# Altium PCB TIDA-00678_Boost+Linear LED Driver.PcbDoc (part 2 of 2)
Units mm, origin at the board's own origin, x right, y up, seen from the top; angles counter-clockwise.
Board outline 111.76 x 61.72 mm, 2 copper layers (Top Layer, Bottom Layer), stack 1.575 mm thick; 183 components, 81 nets, 485 pads, 326 vias.
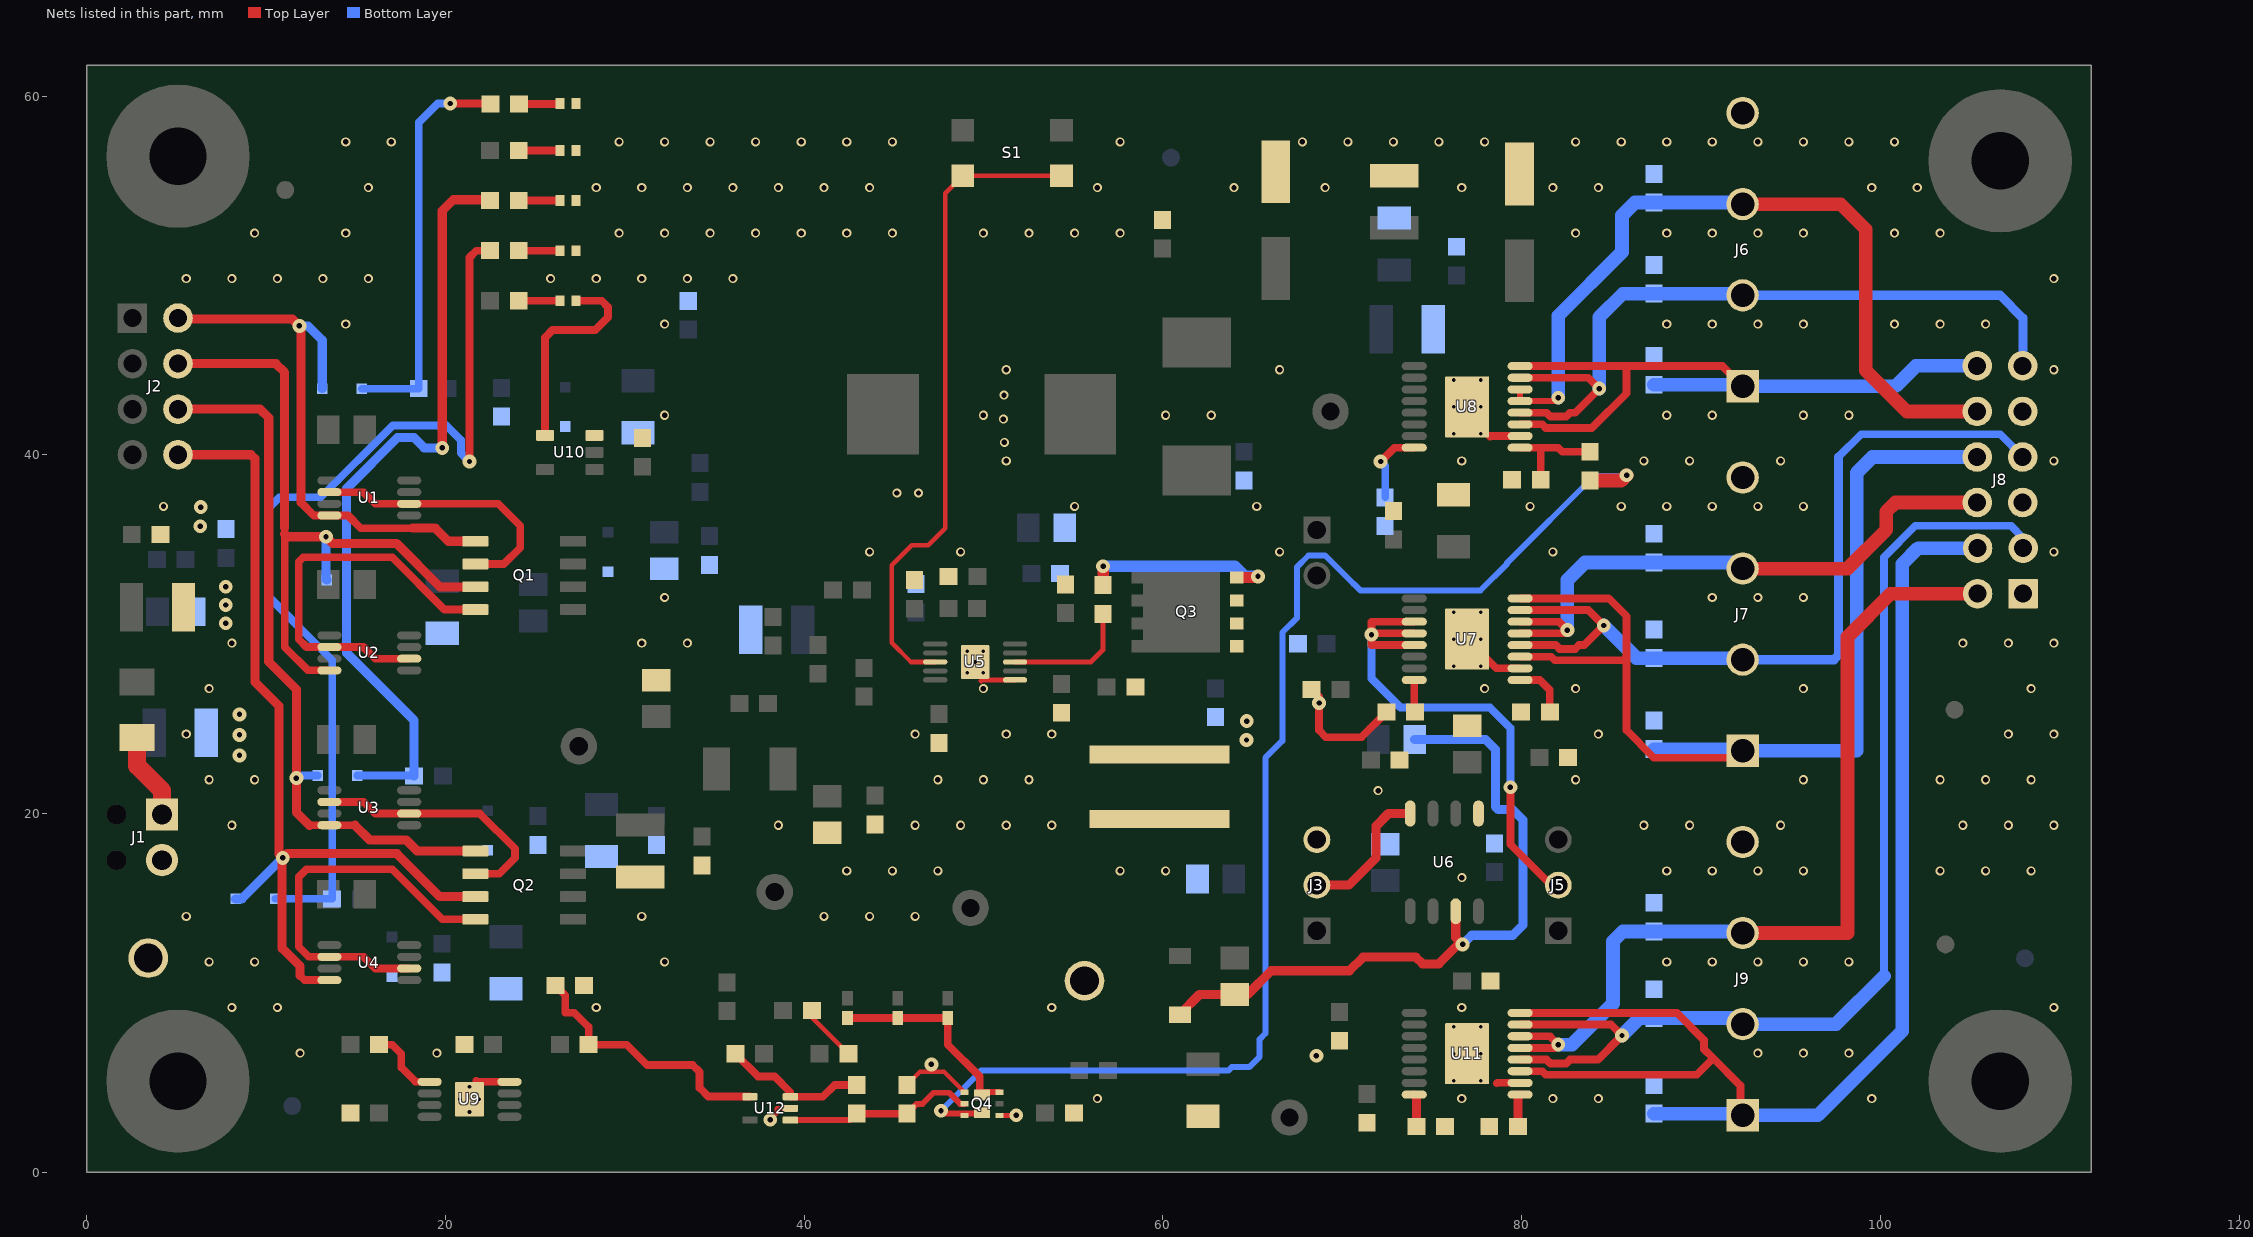
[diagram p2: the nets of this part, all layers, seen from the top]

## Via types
v1: diameter 0.508, hole 0.305, Top Layer to Bottom Layer, tented both sides, 203 vias
v2: diameter 0.77, hole 0.3, Top Layer to Bottom Layer, tented both sides, 96 vias
v3: diameter 0.4, hole 0.2, Top Layer to Bottom Layer, 18 vias
v4: diameter 0.5, hole 0.2, Top Layer to Bottom Layer, 9 vias

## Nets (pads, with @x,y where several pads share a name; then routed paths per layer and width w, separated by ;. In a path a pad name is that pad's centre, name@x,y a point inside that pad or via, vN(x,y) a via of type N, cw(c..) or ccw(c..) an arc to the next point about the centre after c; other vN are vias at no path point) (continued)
NetC67_2: C67.2 Q4.5 R42.1 U12.1 | length 10.6
  Top Layer w0.33: U12.1@39.225,2.906 42.568,2.906 R42.1@42.926,3.264 ; C67.2@45.72,3.264 46.266,3.81 46.592,3.81 47.211,4.429 48.076,4.429 48.695,3.81 Q4.5@48.936,3.81
  Top Layer w0.432: R42.1@42.926,3.264 C67.2@45.72,3.264
NetD2_2: D2.2 R13.1 R14.2 U6.7 | length 39.2
  Top Layer w0.508: D2.2@60.96,8.777 60.96,8.826 62.04,9.906 R14.2@64.008,9.906 64.716,9.906 66.04,11.23 70.397,11.23 71.159,11.992 74.098,11.992 74.479,11.611 75.381,11.611 76.47,12.7 v2(76.708,12.7) 76.327,13.081 U6.7@76.327,14.547
  Bottom Layer w0.508: R13.1@74.041,24.13 77.978,24.13 78.536,23.572 78.536,20.375 78.696,20.215 79.499,20.215 80.083,19.631 80.083,13.789 79.502,13.208 77.216,13.208 v2(76.708,12.7)
NetD3_1: D3.1 R11.2 R15.1 | length 43.7
  Top Layer w0.508: v2(19.812,40.386) 19.812,53.599 20.437,54.224 22.432,54.224 R11.2@22.479,54.177
  Bottom Layer w0.432: D3.1@15.07,22.12 18.228,22.12 R15.1@18.25,22.098
  Bottom Layer w0.508: R15.1@18.25,22.098 18.25,25.184 14.478,28.956 14.478,38.116 17.329,40.967 18.231,40.967 18.812,40.386 v2(19.812,40.386)
NetD4_1: D4.1 R12.2 R16.1 | length 22.5
  Top Layer w0.432: v2(20.259,59.587) 22.475,59.587 R12.2@22.506,59.556
  Bottom Layer w0.432: D4.1@15.324,43.688 R16.1@18.504,43.688 18.504,58.526 19.566,59.587 v2(20.259,59.587)
NetD6_2: D6.2 R11.1 | length 2.3
  Top Layer w0.432: R11.1@24.079,54.177 D6.2@26.385,54.177
NetD8_2: D8.2 R12.1 | length 2.3
  Top Layer w0.432: R12.1@24.106,59.556 26.353,59.556 D8.2@26.384,59.586
NetD10_2: D10.2 R17.1 | length 2.3
  Top Layer w0.432: R17.1@24.079,56.971 D10.2@26.385,56.971
NetD12_1: D12.1 R31.2 R32.1 | length 53.6
  Top Layer w0.432: v2(21.336,39.624) 21.336,50.999 21.72,51.383 R31.2@22.479,51.383 R31.2@22.432,51.43
  Bottom Layer w0.432: D12.1@10.498,15.24 R32.1@13.678,15.24 13.678,28.543 10.125,32.096 10.125,37.011 10.741,37.627 13.041,37.627 17.051,41.637 20.047,41.637 20.863,40.821 20.863,40.097 v2(21.336,39.624)
NetD13_2: D13.2 R31.1 | length 2.3
  Top Layer w0.432: R31.1@24.079,51.383 D13.2@26.385,51.383
NetD15_1: D15.1 U10.4 | length 11.9
  Top Layer w0.432: U10.4@25.549,41.082 25.549,46.541 25.963,46.956 28.344,46.956 29.058,47.67 29.058,48.235 28.704,48.589 D15.1@27.285,48.589
NetD15_2: D15.2 R34.1 | length 2.3
  Top Layer w0.432: R34.1@24.079,48.589 D15.2@26.385,48.589
NetD16_1: D16.1 D17.1 D18.1 Q4.3 Q4.8 | length 11.5
  Top Layer w0.33: Q4.8@49.784,4.554 49.878,4.46 Q4.3@50.886,4.46
  Top Layer w0.432: D16.1@42.418,8.594 D17.1@45.212,8.594 D18.1@48.006,8.594 48.006,7.112 49.784,5.334 Q4.8@49.784,4.554
NetJ1_1: J1.1 L1.1 | length 4.9
  Top Layer w1.016: L1.1@2.794,24.231 2.794,22.666 4.191,21.269 J1.1@4.191,19.939
NetJ3_2: J3.2 U6.4 | length 7.9
  Top Layer w0.508: J3.2@68.58,16.002 70.358,16.002 71.882,17.526 71.882,19.304 72.575,19.997 U6.4@73.787,19.997
NetJ5_2: J5.2 U7.3 U7.4 U7.5 | length 29.9
  Top Layer w0.432: U7.5@74.012,29.393 71.628,29.393 v2(71.628,29.972) v2@71.628,30.043 ; U7.4@74.012,30.043 v2@71.628,30.043 ; U7.3@74.012,30.693 71.646,30.693 71.628,30.675 v2@71.628,30.043 ; v2(79.375,21.463) 79.375,18.288 81.661,16.002 J5.2@82.042,16.002
  Bottom Layer w0.432: v2(71.628,29.972) 71.628,27.526 73.246,25.908 78.232,25.908 79.375,24.765 v2(79.375,21.463)
NetQ1_2: Q1.2 U1.2 U1.6 | length 15.5
  Top Layer w0.432: U1.2@13.523,37.917 15.423,37.917 16.073,37.267 U1.6@17.973,37.267 22.931,37.267 24.159,36.039 24.159,34.827 23.241,33.909 Q1.2@21.659,33.909
NetQ1_4: Q1.4 U2.2 U2.6 | length 22.1
  Top Layer w0.432: U2.6@17.973,28.631 16.073,28.631 15.423,29.281 U2.2@13.523,29.281 12.248,29.281 11.811,29.718 11.811,34.036 12.065,34.29 17.018,34.29 19.939,31.369 Q1.4@21.659,31.369
NetQ2_2: Q2.2 U3.2 U3.6 | length 14.5
  Top Layer w0.432: U3.2@13.523,20.645 15.423,20.645 16.073,19.995 U3.6@17.973,19.995 21.915,19.995 23.876,18.034 23.876,17.526 22.987,16.637 Q2.2@21.659,16.637
NetQ2_4: Q2.4 U4.2 U4.6 | length 21.7
  Top Layer w0.432: U4.6@17.973,11.359 16.073,11.359 15.423,12.009 U4.2@13.523,12.009 12.375,12.009 11.811,12.573 11.811,16.459 12.246,16.894 17.018,16.894 19.815,14.097 Q2.4@21.659,14.097
NetQ3_1: Q3.1 Q3.2 Q3.3 R7.2 R8.2 R9.1
  other v2: 64.659,24.099 64.677,25.151
NetQ3_4: Q3.4 R6.2 | length 11.1
  Top Layer w0.635: R6.2@56.662,32.752 v2(56.662,33.786) ; Q3.4@64.117,33.159 65.241,33.159 v2(65.301,33.219)
  Bottom Layer w0.635: v2(56.662,33.786) 64.019,33.786 64.586,33.219 v2(65.301,33.219)
NetQ4_6: Q4.6 Q4.7 R29.1 | length 74
  Top Layer w0.33: v2(47.625,3.429) 47.774,3.28 49.911,3.28 Q4.7@49.911,3.322
  Top Layer w0.762: R29.1@83.82,38.57 85.56,38.57 v2(85.852,38.862)
  Bottom Layer w0.33: v2@47.498,3.556 v2(47.625,3.429) 49.86,5.664 63.643,5.664 63.837,5.858 64.803,5.858 65.389,6.444 65.389,7.41 65.713,7.734 65.713,23.101 66.661,24.049 66.661,30.09 67.465,30.894 67.465,33.736 68.118,34.389 69.042,34.389 70.628,32.803 70.642,32.803 71.006,32.439 77.711,32.439 79.194,33.922 79.194,33.982 84.032,38.82 85.81,38.82 v2(85.852,38.862)
NetR6_1: R6.1 U5.8 | length 7.2
  Top Layer w0.279: U5.8@51.755,28.448 55.983,28.448 56.646,29.111 R6.1@56.646,31.135
NetR25_2: R25.2 U7.8 | length 1.8
  Top Layer w0.432: U7.8@74.012,27.443 74.012,25.706 R25.2@74.064,25.654
NetR26_2: R26.2 U8.8 | length 4.3
  Top Layer w0.432: v2(72.136,39.624) 72.909,40.397 U8.8@74.012,40.397
  Bottom Layer w0.432: v2(72.136,39.624) 72.39,39.37 R26.2@72.39,37.63
NetR27_2: R27.2 U7.9 | length 3.1
  Top Layer w0.432: U7.9@79.912,27.443 81.015,27.443 81.572,26.886 R27.2@81.572,25.654
NetR28_2: R28.2 R29.2 U8.9 | length 5.8
  Top Layer w0.432: U8.9@79.912,40.397 81.026,40.397 ; R28.2@81.064,38.608 81.064,40.359 81.026,40.397 ; R29.2@83.82,40.17 82.258,40.17 82.031,40.397 81.026,40.397
NetR30_1: R30.1 U9.5 | length 4.1
  Top Layer w0.432: R30.1@16.294,7.112 17.018,7.112 17.526,6.604 17.526,5.842 18.329,5.039 U9.5@19.111,5.039
NetR37_1: R37.1 R38.2 U12.4 | length 15.1
  Top Layer w0.432: R38.2@26.124,10.414 26.67,9.868 26.67,8.89 27.178,8.89 27.978,8.09 R37.1@27.978,7.112 30.099,7.112 31.242,5.969 33.782,5.969 34.163,5.588 34.163,4.699 34.64,4.222 36.959,4.222 U12.4@36.975,4.206
NetR39_2: R39.2 R42.2 U12.3 | length 8.2
  Top Layer w0.432: R39.2@36.157,6.604 37.427,5.334 38.354,5.334 39.225,4.463 U12.3@39.225,4.206 41.036,4.206 41.694,4.864 R42.2@42.926,4.864
NetR40_2: R40.2 U11.8 | length 1.8
  Top Layer w0.508: U11.8@74.012,4.3 74.13,4.182 R40.2@74.13,2.54
NetR41_2: R41.2 U11.9 | length 1.8
  Top Layer w0.508: R41.2@79.794,2.54 79.794,4.182 U11.9@79.912,4.3
NetS1_3: S1.3 S1.4 U5.3 | length 36.6
  Top Layer w0.254: U5.3@47.305,28.448 45.948,28.448 44.873,29.523 44.873,33.832 45.993,34.952 46.905,34.952 47.855,35.902 47.855,54.578 S1.3@48.838,55.56 S1.4@54.338,55.56
REV1: C68.2 J8.4 J9.1 U11.11 U11.16 | length 73.8
  Top Layer w0.432: U11.11@79.912,5.629 81.145,5.629 81.345,5.429 89.757,5.429 90.678,6.35 ; U11.16@79.912,8.879 88.657,8.879 90.17,7.366 90.17,6.858 90.678,6.35 ; J9.1@92.202,2.794 92.202,4.826 90.678,6.35
  Bottom Layer w0.762: C68.2@87.378,3.264 92.11,3.264 ccw(c92.11,3.394) J9.1@92.202,3.302 ; J9.1@92.324,3.175 96.52,3.175 101.219,7.874 101.219,33.909 102.108,34.798 J8.4@105.41,34.798
REV2: C66.2 J8.3 J9.2 U11.12 U11.15 | length 61.3
  Top Layer w0.432: U11.12@79.912,6.279 81.389,6.279 81.607,6.061 82.477,6.061 82.695,6.279 84.257,6.279 v2(85.598,7.62) 84.989,8.229 U11.15@79.912,8.229
  Bottom Layer w0.432: 100.203,10.922 100.203,34.29 101.952,36.039 107.286,36.039 107.95,35.375 J8.3@107.95,34.798
  Bottom Layer w0.762: v2(85.598,7.62) 86.576,8.598 C66.2@87.378,8.598 91.981,8.598 J9.2@92.324,8.255 97.536,8.255 100.203,10.922
REV3: C64.2 J8.2 J9.3 U11.13 U11.14 | length 50.6
  Top Layer w0.432: U11.13@79.912,6.929 81.859,6.929 v2(82.042,7.112) 81.575,7.579 U11.14@79.912,7.579
  Top Layer w0.762: J9.3@92.324,13.335 98.171,13.335 98.171,29.845 100.584,32.258 J8.2@105.41,32.258
  Bottom Layer w0.762: v2(82.042,7.112) 82.804,7.112 85.09,9.398 85.09,12.878 85.636,13.424 C64.2@87.378,13.424 J9.3@91.732,13.424 ; J9.3@92.202,12.954 J9.3@91.732,13.424 ; J9.3@92.202,13.462 cw(c92.11,13.554) 92.11,13.424 J9.3@91.732,13.424
REVGND: C1.2 C2.2 C3.2 C4.2 C5.2 C10.2 C11.2 C12.2 C13.2 C14.2 C15.2 C16.2 C17.2 C20.1 C21.1 C22.1 C23.2 C24.2 C26.2 C27.2 C28.2 C29.2 C30.2 C31.2 C32.1 C33.1 C34.2 C35.1 C36.1 C37.1 C38.2 C39.1 C40.2 C41.1 C42.2 C43.2 C44.1 C45.1 C46.2 C47.2 C48.2 C49.1 C50.1 C51.1 C52.1 C53.1 C54.1 C55.2 C56.1 C57.2 C58.1 C59.2 C60.1 C61.2 C62.1 C63.2 C64.1 C65.1 C66.1 C67.1 C68.1 D6.1 D7.2 D8.1 D9.2 D10.1 D11.2 D13.1 D14.2 GND_1.1 GND_2.1 J1.2 J3.3 J6.4 J7.4 J8.1 J8.5 J8.9 J9.4 Q4.1 Q4.4 R5.1 R8.1 R18.1 R19.1 R23.1 R24.1 R25.1 R26.1 R27.1 R28.1 R33.1 R36.1 R38.1 R40.1 R41.1 U5.6 U5.11 U6.1 U7.10 U7.17 U8.10 U8.17 U9.4 U9.9 U10.3 U11.10 U11.17 U12.2 | length 27.6
  Top Layer w0.254: v2@38.1,3.175 v2(38.1,2.921) 38.481,3.302 38.481,3.556 U12.2@39.225,3.556 ; C67.1@45.72,4.864 46.444,5.588 47.808,5.588 Q4.4@48.936,4.46 ; Q4.1@50.886,3.16 51.801,3.16 v2(51.816,3.175)
  Top Layer w0.279: C63.2@40.424,9.017 40.424,8.636 R36.1@42.456,6.604 ; 49.862,27.376 49.934,27.448 U5.6@51.755,27.448
  Top Layer w0.432: 21.717,5.08 21.758,5.039 U9.4@23.661,5.039 ; C42.2@68.288,26.924 68.707,26.505 v2(68.707,26.162) 68.707,24.638 69.088,24.257 71.067,24.257 R25.1@72.464,25.654 ; U7.17@76.962,29.718 78.587,28.093 U7.10@79.912,28.093 ; 78.232,41.021 78.258,41.047 U8.10@80.012,41.047 ; 78.613,4.953 78.639,4.979 U11.10@80.012,4.979
  other v1: 56.341,4.103 76.661,4.103 81.741,4.103 84.281,4.103 99.521,4.103 11.891,6.643 19.511,6.643 93.171,6.643 95.711,6.643 98.251,6.643 8.081,9.183 10.621,9.183 28.401,9.183 53.801,9.183 76.661,9.183 109.681,9.183 6.811,11.723 9.351,11.723 32.211,11.723 88.091,11.723 90.631,11.723 93.171,11.723 95.711,11.723 98.251,11.723 5.541,14.263 30.941,14.263 41.101,14.263 43.641,14.263 46.181,14.263 76.669,16.422 42.371,16.803 44.911,16.803 47.451,16.803 57.611,16.803 60.151,16.803 88.091,16.803 90.631,16.803 93.171,16.803 95.711,16.803 103.331,16.803 105.871,16.803 108.411,16.803 8.081,19.343 38.561,19.343 46.181,19.343 48.721,19.343 51.261,19.343 53.801,19.343 86.821,19.343 89.361,19.343 94.441,19.343 104.601,19.343 107.141,19.343 109.681,19.343 71.998,21.279 6.811,21.883 9.351,21.883 47.451,21.883 49.991,21.883 52.531,21.883 83.011,21.883 95.711,21.883 103.331,21.883 105.871,21.883 108.411,21.883 5.541,24.423 46.181,24.423 51.261,24.423 53.801,24.423 84.281,24.423 107.141,24.423 109.681,24.423 6.811,26.963 49.991,26.963 77.931,26.963 83.011,26.963 95.711,26.963 108.411,26.963 8.081,29.503 30.941,29.503 33.481,29.503 104.601,29.503 107.141,29.503 109.681,29.503 32.211,32.043 90.631,32.043 93.171,32.043 95.711,32.043 43.641,34.583 48.721,34.583 66.501,34.583 81.741,34.583 109.681,34.583 4.271,37.123 55.071,37.123 65.231,37.123 80.471,37.123 85.551,37.123 88.091,37.123 90.631,37.123 93.171,37.123 95.711,37.123 45.166,37.87 46.37,37.87 51.261,39.663 76.661,39.663 86.821,39.663 89.361,39.663 94.441,39.663 109.681,39.663 51.159,40.687 51.108,41.993 32.211,42.203 49.991,42.203 60.151,42.203 62.691,42.203 88.091,42.203 90.631,42.203 95.711,42.203 98.251,42.203 51.138,43.328 51.261,44.743 66.501,44.743 109.681,44.743 14.431,47.283 32.211,47.283 88.091,47.283 90.631,47.283 93.171,47.283 95.711,47.283 100.791,47.283 103.331,47.283 105.871,47.283 5.541,49.823 8.081,49.823 10.621,49.823 13.161,49.823 15.701,49.823 25.861,49.823 28.401,49.823 30.941,49.823 33.481,49.823 36.021,49.823 109.681,49.823 9.351,52.363 14.431,52.363 29.671,52.363 32.211,52.363 34.751,52.363 37.291,52.363 39.831,52.363 42.371,52.363 44.911,52.363 49.991,52.363 52.531,52.363 55.071,52.363 57.611,52.363 83.011,52.363 88.091,52.363 90.631,52.363 93.171,52.363 95.711,52.363 100.791,52.363 103.331,52.363 15.701,54.903 28.401,54.903 30.941,54.903 33.481,54.903 36.021,54.903 38.561,54.903 41.101,54.903 43.641,54.903 56.341,54.903 63.961,54.903 69.041,54.903 76.661,54.903 81.741,54.903 84.281,54.903 99.521,54.903 102.061,54.903 14.431,57.443 16.971,57.443 29.671,57.443 32.211,57.443 34.751,57.443 37.291,57.443 39.831,57.443 42.371,57.443 44.911,57.443 57.611,57.443 67.771,57.443 70.311,57.443 72.851,57.443 75.391,57.443 77.931,57.443 83.011,57.443 85.551,57.443 88.091,57.443 90.631,57.443 93.171,57.443 95.711,57.443 98.251,57.443 100.791,57.443
  other v2: 47.09,6.009 68.558,6.489 8.509,23.241 8.509,24.384 8.509,25.527 7.747,30.607 7.747,31.623 7.747,32.639 6.316,36.019 6.35,37.084
  other v3: 76.212,5.104 77.712,5.104 76.212,6.604 77.712,6.604 76.212,8.104 77.712,8.104 76.212,28.218 77.712,28.218 76.212,29.718 77.712,29.718 76.212,31.218 77.712,31.218 76.212,41.172 77.712,41.172 76.212,42.672 77.712,42.672 76.212,44.172 77.712,44.172
  other v4: 21.336,3.354 20.786,4.064 21.886,4.064 21.336,4.774 49.08,27.848 49.98,27.848 49.53,28.448 49.08,29.048 49.98,29.048
TB1: C54.2 J6.1 J8.12 U8.11 U8.16 | length 40.3
  Top Layer w0.432: U8.11@79.912,41.697 81.145,41.697 81.345,41.497 83.915,41.497 85.852,43.434 85.852,44.947 ; U8.16@79.912,44.947 85.852,44.947 ; J6.1@92.202,43.434 92.202,43.942 91.197,44.947 85.852,44.947
  Bottom Layer w0.762: C54.2@87.376,43.904 J6.1@91.986,43.904 ; J6.1@92.202,43.688 J6.1@91.986,43.904 ; J6.1@92.202,43.942 cw(c92.11,44.034) 92.11,43.904 J6.1@91.986,43.904 ; J6.1@92.324,43.815 100.838,43.815 101.981,44.958 J8.12@105.41,44.958
TB2: C52.2 J6.2 J8.11 U8.12 U8.15 | length 41.8
  Top Layer w0.432: U8.12@79.912,42.347 81.389,42.347 81.607,42.129 82.477,42.129 82.695,42.347 82.987,42.347 v2(84.328,43.688) 83.719,44.297 U8.15@79.912,44.297
  Bottom Layer w0.508: J6.2@92.324,48.895 106.68,48.895 107.95,47.625 J8.11@107.95,44.958
  Bottom Layer w0.762: v2(84.328,43.688) 84.328,47.676 85.636,48.984 C52.2@87.378,48.984 J6.2@91.732,48.984 ; J6.2@92.072,48.644 J6.2@91.732,48.984 ; J6.2@92.202,48.768 J6.2@91.986,48.984 ; J6.2@92.202,49.022 cw(c92.11,49.114) 92.11,48.984 J6.2@91.986,48.984 ; J6.2@91.732,48.984 J6.2@91.986,48.984
TB3: C50.2 J6.3 J8.10 U8.13 U8.14 | length 44.8
  Top Layer w0.33: U8.14@79.912,43.647 U8.13@79.912,42.997 81.859,42.997 v2(82.042,43.18)
  Top Layer w0.762: J6.3@92.324,53.975 97.79,53.975 99.187,52.578 99.187,44.704 101.473,42.418 J8.10@105.397,42.418
  Bottom Layer w0.762: v2(82.042,43.18) 82.042,47.752 85.598,51.308 85.598,53.34 86.322,54.064 C50.2@87.378,54.064 J6.3@91.732,54.064 ; J6.3@92.202,53.594 J6.3@91.732,54.064 ; J6.3@92.202,53.848 J6.3@91.986,54.064 ; J6.3@92.202,54.102 cw(c92.11,54.194) 92.11,54.064 J6.3@91.986,54.064 ; J6.3@91.732,54.064 J6.3@91.986,54.064
TURN1: C53.2 J7.1 J8.8 U7.11 U7.16 | length 60.5
  Top Layer w0.432: U7.11@79.912,28.743 81.653,28.743 81.853,28.543 85.757,28.543 85.852,28.448 ; U7.16@79.912,31.993 84.847,31.993 85.852,30.988 85.852,28.702 ; 85.811,28.743 85.852,28.702 ; J7.1@92.324,23.495 91.943,23.114 87.376,23.114 85.852,24.638 85.852,28.448 ; 85.852,28.448 85.852,28.702
  Bottom Layer w0.762: C53.2@87.378,23.584 J7.1@91.732,23.584 ; J7.1@92.202,23.114 J7.1@91.732,23.584 ; J7.1@92.202,23.622 cw(c92.11,23.714) 92.11,23.584 J7.1@91.732,23.584 ; J7.1@92.324,23.495 98.679,23.495 98.679,38.989 99.568,39.878 J8.8@105.397,39.878
TURN2: C51.2 J7.2 J8.7 U7.12 U7.15 | length 47
  Top Layer w0.432: U7.12@79.912,29.393 81.897,29.393 82.115,29.175 82.985,29.175 83.203,29.393 83.495,29.393 v2(84.582,30.48) 83.719,31.343 U7.15@79.912,31.343
  Bottom Layer w0.432: 97.663,39.878 98.933,41.148 106.68,41.148 J8.7@107.95,39.878
  Bottom Layer w0.508: J7.2@92.324,28.575 97.409,28.575 97.663,28.829 97.663,39.878
  Bottom Layer w0.762: v2(84.582,30.48) 86.398,28.664 C51.2@87.378,28.664 J7.2@91.732,28.664 ; J7.2@92.072,28.324 J7.2@91.732,28.664 ; J7.2@92.202,28.702 cw(c92.11,28.794) 92.11,28.664 J7.2@91.732,28.664
TURN3: C49.2 J7.3 J8.6 U7.13 U7.14 | length 33.9
  Top Layer w0.432: U7.13@79.912,30.043 82.367,30.043 v2(82.55,30.226) 82.083,30.693 U7.14@79.912,30.693
  Top Layer w0.762: J7.3@92.324,33.655 98.171,33.655 100.33,35.814 100.33,36.83 100.838,37.338 J8.6@105.41,37.338
  Bottom Layer w0.762: v2(82.55,30.226) 82.55,33.02 83.528,33.998 C49.2@87.378,33.998 91.981,33.998 J7.3@92.324,33.655
"VIN 1": D4.2 J2.2 Q1.1 U1.4 | length 31.8
  Top Layer w0.432: 11.938,37.338 12.659,36.617 U1.4@13.523,36.617 14.561,36.617 15.268,35.91 18.146,35.91
  Top Layer w0.508: J2.2@5.08,47.625 5.132,47.573 11.462,47.573 v2(11.847,47.188) 11.938,47.097 11.938,37.338 ; 18.146,35.91 19.423,35.91 20.154,35.179 Q1.1@21.659,35.179
  Bottom Layer w0.508: v2(11.847,47.188) 12.325,47.188 13.124,46.389 D4.2@13.124,43.688
"VIN 2": D5.2 J2.4 Q1.3 U2.4 | length 38.8
  Top Layer w0.432: 11.029,35.95 11.029,35.58 11.029,29.279 12.327,27.981 U2.4@13.523,27.981 U2.4@13.514,27.99
  Top Layer w0.508: J2.4@5.08,45.085 10.541,45.085 11.029,44.597 11.029,35.95 ; 11.029,35.58 11.176,35.433 v2(13.335,35.433) 13.716,35.052 17.272,35.052 19.685,32.639 Q1.3@21.659,32.639
  Bottom Layer w0.508: v2(13.335,35.433) 13.335,33.063 D5.2@13.378,33.02
"VIN 3": D3.2 J2.6 Q2.1 U3.4 | length 40
  Top Layer w0.432: 12.405,19.345 U3.4@13.523,19.345 14.945,19.345
  Top Layer w0.508: J2.6@5.08,42.545 9.652,42.545 10.142,42.055 10.142,28.466 11.684,26.924 v2(11.684,21.971) 11.684,20.066 12.405,19.345 ; 14.945,19.345 15.77,18.52 17.802,18.52 18.415,17.907 Q2.1@21.659,17.907
  Bottom Layer w0.432: v2(11.684,21.971) 11.833,22.12 D3.2@12.87,22.12
"VIN 4": D12.2 J2.8 Q2.3 U4.4 | length 51.4
  Top Layer w0.432: 11.889,10.961 12.141,10.709 U4.4@13.523,10.709
  Top Layer w0.508: J2.8@5.08,40.005 9.144,40.005 9.366,39.783 9.366,27.336 10.706,25.996 10.706,17.742 v2@10.883,17.565 ; 11.889,10.961 11.889,11.479 10.883,12.485 v2@10.883,17.565 ; Q2.3@21.659,15.367 19.685,15.367 17.289,17.763 11.159,17.763 v2(10.922,17.526) v2@10.883,17.565
  Bottom Layer w0.508: D12.2@8.298,15.24 8.636,15.24 v2(10.922,17.526)
pads on no net: FID1.1 FID2.1 FID3.1 FID4.1 FID5.1 FID6.1 H1.0 H2.1 H3.0 H4.1 H5.0 H6.1 H7.0 H8.1 J1.MH1 J1.MH2 U1.3 U1.5 U2.3 U2.5 U3.3 U3.5 U4.3 U4.5 U9.2 U9.3 U9.6 U9.7 U10.1

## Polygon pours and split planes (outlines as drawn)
REVGND on Top Layer "TopFill" (solid, remove dead copper, pour order 23): 0,61.741 111.76,61.741 111.76,0 0,0
BOOST_IN on Top Layer "Boost DC" (solid, remove dead copper, pour order 37): 49.098,33.741 50.264,33.741 50.276,33.729 50.476,33.529 50.476,31.998 50.476,31.974 50.606,31.845 52.419,31.845 52.454,31.845 52.607,31.692 52.678,31.621 52.678,29.231 50.994,29.231 50.924,29.301 50.865,29.36 50.865,30.561 50.535,30.891 50.523,30.879 49.039,30.879
BOOST_IN on Top Layer "Lin" (solid, remove dead copper, pour order 35): 39.936,44.204 40.441,44.71 40.441,44.802 46.665,44.802 46.872,44.595 46.78,44.503 46.78,39.082 40.556,39.082 39.936,39.703 39.913,39.726 39.913,44.227
NetC25_1 on Top Layer "SWNode" (solid, remove dead copper, pour order 34): 53.138,44.742 58.077,44.742 58.739,44.081 58.743,41.076 58.832,41.076 59.15,40.757 59.27,40.638 63.821,40.638 63.821,37.544 63.901,37.464 63.901,28.741 57.713,28.741 57.434,29.021 57.434,39.121 53.442,39.121 53.142,39.42 53.142,44.729
BOOST_IN on Top Layer "Boostadd" (solid, remove dead copper, pour order 32): 37.474,27.225 38.825,27.225 38.965,27.086 39.154,26.897 39.154,23.133 38.208,23.133 37.973,23.368 37.964,23.377 37.964,25.295 37.776,25.295 37.475,25.595 37.489,25.609 37.489,27.212
NetC10_1 on Top Layer "RBadd" (solid, remove dead copper, pour order 30): 33.185,26.416 33.186,26.417 33.186,27.033 33.186,27.058 33.388,27.26 33.401,27.273 36.872,27.273 36.872,25.102 36.569,24.799 36.455,24.913 33.199,24.913 33.185,24.926 33.185,26.416
BOOST_IN on Top Layer "BoostIN" (solid, remove dead copper, pour order 29): 37.973,23.622 37.973,20.955 38.735,20.955 39.751,19.939 42.291,19.939 42.672,19.939 43.053,20.32 43.18,20.193 44.958,20.193 44.958,23.368 44.323,24.003 38.354,24.003 38.227,24.13 37.973,23.876 37.973,23.749
NetC10_1 on Top Layer "RB Polyq" (solid, remove dead copper, pour order 24): 25.781,36.195 25.781,28.829 25.781,13.716 25.908,13.589 28.829,13.589 28.829,18.288 28.956,18.415 33.147,18.415 33.147,18.161 33.401,17.907 35.941,17.907 35.941,24.765 34.29,26.416 31.877,26.416 30.226,26.416 29.337,27.305 29.083,27.559 29.083,36.068 25.908,36.068 25.781,36.195
NetC2_1 on Top Layer "TFilterVia" (solid, remove dead copper, pour order 21): 1.651,26.543 1.778,26.67 5.461,26.67 5.461,29.21 5.207,29.464 2.032,29.464 1.905,29.464 1.651,29.21 1.651,26.67
NetQ3_1 on Top Layer "Top Layer-No Net 3" (solid, remove dead copper, pour order 26): 63.107,32.187 63.107,28.544 58.321,28.544 57.392,27.615 57.138,27.361 57.138,25.583 56.376,25.583 54.852,24.059 54.852,22.547 65.52,22.547 65.52,25.202 65.52,31.679 65.012,32.187
BOOST_OUT on Top Layer "DiodeKat" (solid, remove dead copper, pour order 33): 59.011,51.978 59.075,51.978 59.351,52.254 59.372,52.275 64.043,52.275 64.659,52.275 65.084,52.7 65.169,52.785 70.392,52.785 71.284,53.677 71.305,53.698 75.764,53.698 75.998,53.698 77.399,52.296 81.285,52.296 81.391,52.296 81.922,51.766 81.943,51.744 81.943,47.922 81.943,47.816 81.646,47.519 81.603,47.477 79.055,47.477 78.694,47.477 77.569,48.602 65.19,48.602 64.85,48.602 64.383,48.135 64.298,48.05 64.298,44.419 63.916,44.037 60.115,44.037 60.094,44.037 59.372,44.759 59.011,45.12 59.011,51.936
REVGND on Bottom Layer "BottFill" (solid, remove dead copper, pour order 25): 0,61.741 0.019,61.722 111.76,61.722 111.76,0 0,0
BOOST_IN on Bottom Layer "DCinBott" (solid, remove dead copper, pour order 38): 51.765,36.812 51.756,36.802 51.756,32.607 51.756,32.101 51.503,31.848 51.454,31.799 50.734,31.799 50.734,31.79 50.578,31.634 50.568,31.624 50.568,30.31 50.568,30.233 50.821,29.98 50.928,29.872 52.563,29.872 52.68,29.989 52.67,29.999 52.67,32.121 52.67,32.14 53.323,32.792 53.293,32.821 53.293,36.841
BOOST_IN on Bottom Layer "Boostin Bottom" (solid, remove dead copper, pour order 36): 42.422,44.45 42.422,40.344 41.201,39.123 41.201,24.882 41.201,24.845 41.978,24.068 42.163,23.883 44.308,23.883 44.308,22.071 43.901,21.664 43.864,21.701 39.759,21.701 39.093,22.367 38.908,22.552 38.908,32.058 38.908,33.501 39.87,34.463 40.017,34.611 40.017,44.524
NetC2_1 on Bottom Layer "FilterViaBot" (solid, remove dead copper, pour order 22): 4.445,23.161 4.445,25.861 4.445,26.035 5.461,27.051 5.461,29.591 5.334,29.591 4.572,30.353 4.572,32.131 3.048,32.131 2.921,32.004 3.048,31.877 3.048,23.241 3.048,23.114 4.445,23.114
NetC25_1 on Bottom Layer "Snub1" (solid, remove dead copper, pour order 27): 63.257,32.713 60.385,32.713 60.034,32.362 60.018,32.346 60.018,31.054 60.018,31.022 60.242,30.799 60.258,30.815 63.065,30.815 63.097,30.815 63.305,31.022 63.369,31.086 63.369,32.585
NetQ3_1 on Bottom Layer "Snub2" (solid, remove dead copper, pour order 28): 62.271,25.819 62.442,25.99 62.442,25.999 63.532,25.999 63.55,25.981 63.802,25.729 63.802,25.647 65.025,25.647 65.164,25.508 65.16,25.504 65.16,23.722 65.16,23.706 65.034,23.58 65.03,23.575 64.135,23.575 64.131,23.575 63.997,23.71 63.925,23.781 63.925,24.357 63.925,24.424 63.568,24.781 63.53,24.819 62.413,24.819 62.27,24.962
BOOST_OUT on Bottom Layer "BoOutB" (solid, remove dead copper, pour order 31): 68.83,50.562 69.346,51.078 69.411,51.078 73.914,51.078 74.102,50.89 74.11,50.882 74.11,49.523 74.11,49.506 73.881,49.277 73.824,49.22 73.333,49.22 73.284,49.22 73.095,49.032 72.981,48.917 72.981,45.773 72.981,45.683 72.743,45.446 72.62,45.323 71.04,45.323 71.016,45.323 70.754,45.585 70.598,45.741 70.598,48.409 70.598,48.45 70.296,48.753 69.059,48.753 69.043,48.753 68.814,48.982

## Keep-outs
Keep-Out Layer:
  lines w0.254: 0,0 0,61.741 111.76,61.741 111.76,0 0,0
  text ".Layer_Name" at 14.656,-21.806 h1.52

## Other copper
Top Layer:
  rectangle net REVGND: 50.544,26.963 52.352,27.552
  pour cut-out: 54.913,21.6 54.913,21.567 55.459,21.021 55.322,20.884 54.852,20.884 54.852,21.539
  pour cut-out: 32.766,22.606 32.766,21.209 33.909,21.209 33.909,22.606
  pour cut-out: 64.795,22.49 64.812,22.473 65.567,22.473 65.567,23.333 65.584,23.35
  text ".Layer_Name" at 14.656,-21.806 h1.52
Bottom Layer:
  text ".Layer_Name" at 14.656,-21.806 h1.52

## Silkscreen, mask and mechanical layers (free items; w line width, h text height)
Top Overlay:
  lines w0.254: 13.666,47.46 13.666,61.145 42.375,61.145 42.375,47.46 13.666,47.46
  text "TAIL LIGHT" at 29.121,59.257 h1.02
  text "GND" at 98.933,58.039 h1.02 r90
  text "BRAKE LIGHT" at 29.121,56.463 h1.02
  text "TURN LIGHT" at 29.121,53.669 h1.02
  text "OUT3" at 98.933,53.086 h1.02 r90
  text "FAULT" at 49.749,53.004 h0.8
  text "RESTART" at 49.661,51.684 h0.8
  text "REVERSE LIGHT" at 29.121,50.875 h1.02
  text "Boost Version" at 0.447,50.507 h1.02
  text "FAULT" at 29.121,48.081 h1.02
  text "OUT2" at 98.806,48.006 h1.02 r90
  text "TAIL" at 6.713,47.108 h1.02
  text "2" at 104.775,46.99 h1.02
  text "1" at 107.696,46.99 h1.02
  text "TAIL/BRAKE" at 101.346,46.482 h1.02 r90
  text "BRAKE" at 6.801,44.776 h1.02
  text "OUT1" at 98.933,43.18 h1.02 r90
  text "TURN" at 6.713,42.355 h1.02
  text "REAR" at 6.669,39.847 h1.02
  text "GND" at 99.06,37.846 h1.02 r90
  text "F" at 66.206,35.359 h1.02
  text "OUT3" at 99.06,32.766 h1.02 r90
  text "FS" at 65.326,32.631 h1.02
  text "12" at 104.521,29.591 h1.02
  text "11" at 107.442,29.591 h1.02
  text "TURN" at 101.219,29.083 h1.02 r90
  text "OUT2" at 99.06,27.686 h1.02 r90
  text ".PCB_E1" at 110.363,25.527 h1.52 r90
  text "OUT1" at 99.187,22.987 h1.02 r90
  text "VIN" at 4.904,22.259 h1.02
  text "+" at 8.331,19.524 h1.02
  text "GND" at 99.187,17.78 h1.02 r90
  text "-" at 8.301,16.819 h1.02
  text "ON" at 84.836,16.764 h1.02 r90
  text "BLINK" at 80.518,13.716 h1.02 r90
  text "OFF" at 84.836,12.954 h1.02 r90
  text "OUT3" at 99.187,12.446 h1.02 r90
  text "TIDA-00678" at 110.363,10.287 h1.52 r90
  text "REAR" at 101.219,9.525 h1.02 r90
  text "OUT2" at 99.187,7.493 h1.02 r90
  text "OUT1" at 99.314,2.667 h1.02 r90
  text ".Layer_Name" at 14.656,-21.806 h1.52
Bottom Overlay:
  text ".Layer_Name" at 14.656,-21.806 h1.52
Top Paste:
  text ".Layer_Name" at 14.656,-21.806 h1.52
Bottom Paste:
  text ".Layer_Name" at 14.656,-21.806 h1.52
Top Solder:
  text ".Layer_Name" at 14.656,-21.806 h1.52
  text ".Layer_Name" at 14.656,-21.806 h1.52
Bottom Solder:
  text ".Layer_Name" at 14.656,-21.806 h1.52
Drill Guide:
  text ".Layer_Name" at 14.656,-21.806 h1.52
M1 Board Outline:
  lines w0.254: -159.004,8.636 -47.244,8.636 ; 0,0 111.76,0 111.76,61.722 0,61.722 0,0
  text ".Layer_Name" at 14.656,-21.806 h1.52
M2 Board Dimensions:
  rectangle: 3.175,-10.16 12.7,-6.985
  rectangle: 0,-6.985 3.175,-3.81
  lines w0.178: 0,-6.985 25.4,-6.985 ; 3.175,-10.16 3.175,-3.81 ; 6.35,-10.16 6.35,-3.81 ; 12.7,-10.16 12.7,-3.81 ; 19.05,-10.16 19.05,-3.81 ; 0,-10.16 0,-3.81 25.4,-3.81 25.4,-10.16 0,-10.16
  text ".Layer_Name" at 14.656,-21.806 h1.52
M3 3D STEP Top:
  text ".Layer_Name" at 14.656,-21.806 h1.52
M4 3D STEP Bottom:
  text ".Layer_Name" at 14.656,-21.806 h1.52
M5 Assembly Top:
  lines w0.254: -7.417,-23.626 160.223,-23.626 ; -7.417,-18.462 160.274,-18.462 ; -7.417,-13.297 -7.417,-28.791 94.31,-28.791 160.274,-28.791 160.274,-13.297 -7.404,-13.297 -7.404,-28.791 32.614,-28.791 ; 55.194,-28.791 55.194,-13.297 ; 87.376,-18.462 87.376,-13.297 ; 108.712,-18.462 108.712,-13.297 ; 124.511,-28.956 124.511,-23.804
  text "COMPONENTS MARKED 'DNP' SHOULD NOT BE POPULATED." at 29.299,-8.09 h1.52
  text "ASSEMBLY VARIANT:" at 29.286,-11.024 h1.52
  text ".VariantName" at 55.601,-11.024 h1.52
  text "PCB VIEWED FROM TOP SIDE" at -5.804,-16.654 h1.52
  text "BOARD #:" at 57.099,-16.654 h1.52
  text ".PRJ_Number" at 70.955,-16.654 h1.52
  text "REV:" at 92.405,-16.654 h1.52
  text ".PCB_Rev" at 99.809,-16.654 h1.52
  text "SVN REV:" at 113.69,-16.654 h1.52
  text ".VersionControl_RevNumber" at 126.543,-16.654 h1.52
  text "TID #:" at 57.099,-21.819 h1.52
  text ".TID" at 70.955,-21.819 h1.52
  text "PLOT NAME =" at -5.804,-27.034 h1.52
  text ".plot_File_Name" at 14.656,-27.034 h1.52
  text "GENERATED    :" at 57.15,-27.034 h1.52
  text ".Print_Date" at 79.235,-27.034 h1.52
  text ".Print_Time" at 97.752,-27.034 h1.52
  text "TEXAS INSTRUMENTS" at 129.87,-27.034 h1.52
M6 Assembly Bottom:
  lines w0.254: -7.429,-18.474 160.261,-18.474 ; -7.379,-23.639 160.261,-23.639 ; 28.334,-28.969 28.334,-23.817 ; 44.133,-18.474 44.133,-13.31 ; 65.468,-18.474 65.468,-13.31 ; 97.65,-28.804 97.65,-13.31 ; 120.231,-28.804 160.249,-28.804 160.249,-13.31 -7.429,-13.31 -7.429,-28.804 58.534,-28.804 160.261,-28.804 160.261,-13.31
  text "COMPONENTS MARKED 'DNP' SHOULD NOT BE POPULATED." at 154.991,-8.077 h1.52
  text ".VariantName" at 128.473,-11.024 h1.52
  text "ASSEMBLY VARIANT:" at 154.864,-11.024 h1.52
  text ".VersionControl_RevNumber" at 26.302,-16.667 h1.52
  text "SVN REV:" at 39.154,-16.667 h1.52
  text ".PCB_Rev" at 53.035,-16.667 h1.52
  text "REV:" at 60.439,-16.667 h1.52
  text ".PRJ_Number" at 81.89,-16.667 h1.52
  text "BOARD #:" at 95.745,-16.667 h1.52
  text "PCB VIEWED FROM BOTTOM SIDE" at 158.648,-16.667 h1.52
  text ".TID" at 81.89,-21.831 h1.52
  text "TID #:" at 95.745,-21.831 h1.52
  text "TEXAS INSTRUMENTS" at 22.974,-27.047 h1.52
  text ".Print_Time" at 55.093,-27.047 h1.52
  text ".Print_Date" at 73.609,-27.047 h1.52
  text "GENERATED    :" at 95.694,-27.047 h1.52
  text ".plot_File_Name" at 138.189,-27.047 h1.52
  text "PLOT NAME =" at 158.648,-27.047 h1.52
M9 Title Sheet:
  drawing of 57 lines, arcs and shapes, not listed
  text "1" at 18.792,204.127 h1.78
  text "2" at 82.182,204.127 h1.78
  text "3" at 145.411,204.127 h1.78
  text "4" at 209.08,204.127 h1.78
  text "5" at 272.555,204.127 h1.78
  text "6" at 336.182,204.127 h1.78
  text "A" at -10.579,175.095 h1.78
  text "A" at 365.341,175.095 h1.78
  text "B" at -10.579,114.643 h1.78
  text "B" at 365.341,114.643 h1.78
  text "C" at -10.579,54.318 h1.78
  text "C" at 365.341,54.318 h1.78
  text "PROJECT TITLE:" at 288.125,7.048 h1.14
  text ".PRJ_Title" at 289.395,3.662 h1.78
  text "DESIGNED FOR:" at 288.125,-0.597 h1.14
  text ".PRJ_Customer" at 289.395,-4.153 h1.78
  text "D" at -10.579,-5.88 h1.78
  text "D" at 365.341,-5.88 h1.78
  text "FILE NAME:" at 288.125,-8.217 h1.14
  text ".PCB_File_Name_No_Path" at 289.395,-11.265 h1.78
  text "Texas Instruments (TI) and/or its licensors do not warrant the accuracy or completeness of this specification" at 161.9,-15.376 h1.14
  text "ENGINEER:" at 288.125,-15.583 h1.14
  text "LAYOUT BY:" at 326.352,-15.583 h1.14
  text "or any information contained therein. TI and/or its licensors do not warrant that this design will meet" at 160.757,-18.237 h1.14
  text ".PRJ_Engineer" at 289.395,-19.52 h1.78
  text ".PCB_Layout" at 327.635,-19.52 h1.78
  text "the specifications, will be suitable for your application or fit for any particular purpose, or will operate in" at 160.757,-21.099 h1.14
  text ".Layer_Name" at 14.656,-21.806 h1.52
  text "ALTIUM DESIGNER VERSION:" at 326.352,-23.457 h1.14
  text "an implementation. TI and/or its licensors do not warrant that the design is production worthy. You should" at 160.757,-23.961 h1.14
  text "completely validate and test your design implementation to confirm the system functionality for your application." at 161.9,-26.822 h1.14
  text ".print_Scale" at 289.395,-26.843 h1.78
  text ".Application_BuildNumber" at 327.635,-26.843 h1.78
  text "1" at 18.792,-32.093 h1.78
  text "2" at 82.182,-32.093 h1.78
  text "3" at 145.411,-32.093 h1.78
  text "4" at 209.08,-32.093 h1.78
  text "5" at 272.555,-32.093 h1.78
  text "6" at 336.182,-32.093 h1.78
M10 Fab Notes:
  drawing of 189 lines, arcs and shapes, not listed
  text "DESIGN INFORMATION" at 314.478,153.111 h1.52
  text "MIN. TRACK WIDTH:" at 298.106,148.539 h1.52
  text "8" at 325.951,148.539 h1.52
  text "MIL" at 329.881,148.539 h1.52
  text "MIN. CLEARANCE:" at 298.106,145.186 h1.52
  text "0.2" at 324.427,145.186 h1.52
  text "mm" at 329.881,145.186 h1.52
  text "MIN. VIA PAD SIZE:" at 298.106,141.834 h1.52
  text "24" at 325.189,141.834 h1.52
  text "MIL" at 329.881,141.834 h1.52
  text "0.05mm (2MIL)" at 315.759,138.234 h1.52
  text "MINIMUM ANNULAR RING" at 289.744,138.125 h1.52
  text "EXTERNAL" at 333.742,138.125 h1.52
  text "PER" at 294.824,135.128 h1.52
  text "IPC-D-275 CLASS 2 LEVEL C" at 300.412,135.128 h1.52
  text "MIL, HOLES" at 338.213,132.276 h1.52
  text "+/-" at 328.244,132.258 h1.52
  text "+/-" at 349.936,132.258 h1.52
  text "REGISTRATION TOLERANCES:" at 289.744,132.131 h1.52
  text "METAL" at 320.218,132.131 h1.52
  text "5" at 334.853,132.131 h1.52
  text "3" at 356.012,132.131 h1.52
  text "MIL" at 358.964,132.131 h1.52
  text "+/-" at 349.936,129.261 h1.52
  text "HOLE SIZE TOLERANCE (UNLESS OTHERWISE SPECIFIED):" at 289.744,129.134 h1.52
  text "3" at 356.012,129.134 h1.52
  text "MIL" at 358.964,129.134 h1.52
  text "MATERIAL:" at 287.844,123.813 h1.52
  text "FR-4 High Tg" at 312.9,120.249 h1.52
  text "FR-408" at 298.538,120.031 h1.52
  text "OTHER" at 336.333,120.031 h1.52
  text "X" at 308.966,119.939 h1.52
  text "62 MIL (1.6mm) +/-10%" at 306.668,115.898 h1.52
  text "THICKNESS:" at 289.744,115.789 h1.52
  text "X" at 303.413,115.789 h1.52
  text "OTHER" at 339.305,115.789 h1.52
  text "TOLERANCE:" at 289.744,111.776 h1.52
  text "X" at 311.062,111.776 h1.52
  text "ANSI IPC-6012 TYPE 3 CLASS 2" at 315.81,111.776 h1.52
  text "OTHER +/-" at 315.81,107.814 h1.52
  text "BOW & TWIST:" at 289.744,103.826 h1.52
  text "X" at 311.062,103.826 h1.52
  text "ANSI IPC-6012 TYPE 3 CLASS 2" at 315.81,103.826 h1.52
  text "OTHER +/-" at 315.81,99.8 h1.52
  text "DRILLING:" at 287.844,96.282 h1.52
  text "REFERENCE:" at 289.744,93.31 h1.52
  text "X" at 306.209,93.31 h1.52
  text "AS SHOWN" at 310.958,93.31 h1.52
  text "X" at 329.094,93.31 h1.52
  text "NC_DRILL FILES" at 332.574,93.31 h1.52
  text "PTH MIN COPPER THICKNESS:" at 289.744,89.297 h1.52
  text "X" at 324.039,89.297 h1.52
  text "1MIL" at 327.519,89.297 h1.52
  text "OTHER" at 340.143,89.297 h1.52
  text "BOARD FINISH:" at 287.844,85.259 h1.52
  text "SILKSCREEN:" at 291.787,82.261 h1.52
  text "X" at 315.886,82.261 h1.52
  text "TOP" at 319.086,82.261 h1.52
  text "X" at 328.84,82.261 h1.52
  text "BOTTOM" at 332.066,82.261 h1.52
  text "SILKSCREEN COLOR:" at 291.787,78.02 h1.52
  text "X" at 315.86,78.02 h1.52
  text "WHITE" at 319.086,78.02 h1.52
  text "OTHER" at 332.066,78.02 h1.52
  text "X" at 319.187,73.976 h1.52
  text "GREEN" at 322.414,73.976 h1.52
  text "OTHER" at 338.111,73.976 h1.52
  text "SOLDER RESIST COLOR:" at 291.787,73.702 h1.52
  text "X" at 319.187,69.658 h1.52
  text "MATTE" at 322.414,69.658 h1.52
  text "SEMI-GLOSS" at 338.099,69.642 h1.52
  text "IMMERSION GOLD (ENIG)" at 314.794,64.87 h1.52
  text "ENEPIG" at 348.767,64.786 h1.52
  text "SURFACE FINISH:" at 287.844,64.761 h1.52
  text "X" at 310.045,64.761 h1.52
  text "IMM. TIN/SILVER OR EQUIV" at 296.215,60.773 h1.52
  text "OTHER" at 332.574,60.773 h1.52
  text "ARRAY/PANEL:" at 287.844,56.226 h1.52
  text "CUT AND TRIM PER M1 BOARD OUTLINE" at 314.794,56.118 h1.52
  text "N.C. ROUTE" at 314.794,52.264 h1.52
  text "X" at 332.04,52.264 h1.52
  text "V. SCORE" at 336.79,52.264 h1.52
  text "CERTIFICATION:" at 287.844,48.784 h1.52
  text "MATERIALS AND WORKMANSHIP FOR ALL PCBS" at 306.259,48.784 h1.52
  text "TO MEET OR EXCEED THE REQUIREMENTS OF:" at 306.259,46.295 h1.52
  text "X" at 296.773,42.828 h1.52
  text "ANSI IPC-A-600F CLASS ->" at 300.303,42.828 h1.52
  text "X" at 341.935,42.828 h1.52
  text "2" at 344.956,42.828 h1.52
  text "1" at 336.955,42.79 h1.52
  text "3" at 353.948,42.79 h1.52
  text "X" at 296.825,38.777 h1.52
  text "UL 94V-0" at 300.303,38.777 h1.52
  text "X" at 317.45,38.777 h1.52
  text "RoHS" at 320.928,38.777 h1.52
  text "OTHER" at 337.296,38.777 h1.52
  text "PER ORDER" at 347.381,38.777 h1.52
  text "ADDITIONAL REQUIREMENTS:" at 287.844,35.195 h1.52
  text "MICROSECTION:" at 289.744,32.274 h1.52
  text "YES" at 312.749,32.274 h1.52
  text "REQUIRED" at 334.631,28.308 h1.52
  text "BARE BOARD ELEC. TEST:" at 289.744,28.236 h1.52
  text "NONE" at 322.909,28.236 h1.52
  text "X" at 331.405,28.236 h1.52
  text "PER ORDER" at 349.668,28.236 h1.52
  text "MANUFACTURER'S UL:" at 289.744,24.248 h1.52
  text "RAIL" at 319.353,24.139 h1.52
  text "METAL" at 331.845,24.139 h1.52
  text "X" at 341.376,24.13 h1.52
  text "SILK" at 344.842,24.139 h1.52
  text ".Layer_Name" at 14.656,-21.806 h1.52
M11 Gerber Information:
  lines w0.254: -7.417,-23.626 160.223,-23.626 ; -7.417,-18.462 160.274,-18.462 ; -7.417,-13.297 -7.417,-28.791 94.31,-28.791 160.274,-28.791 160.274,-13.297 -7.404,-13.297 -7.404,-28.791 32.614,-28.791 ; 55.194,-28.791 55.194,-13.297 ; 87.376,-18.462 87.376,-13.297 ; 108.712,-18.462 108.712,-13.297 ; 124.511,-28.956 124.511,-23.804
  text "ALL ARTWORK VIEWED FROM TOP SIDE" at -5.804,-16.654 h1.52
  text "BOARD #:" at 57.099,-16.654 h1.52
  text ".PRJ_Number" at 70.955,-16.654 h1.52
  text "REV:" at 92.405,-16.654 h1.52
  text ".PCB_Rev" at 99.809,-16.654 h1.52
  text "SVN REV:" at 113.69,-16.654 h1.52
  text ".VersionControl_RevNumber" at 126.543,-16.654 h1.52
  text "LAYER NAME =" at -5.804,-21.806 h1.52
  text "TID #:" at 57.099,-21.819 h1.52
  text ".TID" at 70.955,-21.819 h1.52
  text "PLOT NAME =" at -5.804,-27.034 h1.52
  text ".plot_File_Name" at 14.656,-27.034 h1.52
  text "GENERATED    :" at 57.15,-27.034 h1.52
  text ".Print_Date" at 79.235,-27.034 h1.52
  text ".Print_Time" at 97.752,-27.034 h1.52
  text "TEXAS INSTRUMENTS" at 129.87,-27.034 h1.52
M12 Stackup:
  drawing of 191 lines, arcs and shapes, not listed
  text "Layer" at 248.681,198.882 h1.52
  text "Name" at 259.092,198.882 h1.52
  text "Material" at 282.708,198.882 h1.52
  text "Thickness" at 304.546,198.882 h1.52
  text "Constant" at 321.052,198.882 h1.52
  text "Board Layer Stack" at 335.526,198.882 h1.52
  text "1" at 248.681,195.834 h1.52
  text "Top Overlay" at 259.092,195.834 h1.52
  text "2" at 248.681,192.786 h1.52
  text "Top Solder" at 259.092,192.786 h1.52
  text "Solder Resist" at 282.708,192.786 h1.52
  text "0.40mil" at 304.546,192.786 h1.52
  text "3.5" at 321.052,192.786 h1.52
  text "3" at 248.681,189.738 h1.52
  text "Top Layer" at 259.092,189.738 h1.52
  text "Copper" at 282.708,189.738 h1.52
  text "1.40mil" at 304.546,189.738 h1.52
  text "4" at 248.681,186.69 h1.52
  text "Dielectric1" at 259.092,186.69 h1.52
  text "FR-4" at 282.708,186.69 h1.52
  text "59.20mil" at 304.546,186.69 h1.52
  text "4.8" at 321.052,186.69 h1.52
  text "5" at 248.681,183.642 h1.52
  text "Bottom Layer" at 259.092,183.642 h1.52
  text "Copper" at 282.708,183.642 h1.52
  text "1.40mil" at 304.546,183.642 h1.52
  text "6" at 248.681,180.594 h1.52
  text "Bottom Solder" at 259.092,180.594 h1.52
  text "Solder Resist" at 282.708,180.594 h1.52
  text "0.40mil" at 304.546,180.594 h1.52
  text "3.5" at 321.052,180.594 h1.52
  text "7" at 248.681,177.546 h1.52
  text "Bottom Overlay" at 259.092,177.546 h1.52
  text ".Layer_Name" at 14.656,-21.806 h1.52
M13 Component Bodies Top:
  text ".Layer_Name" at 14.656,-21.806 h1.52
M14 Component Bodies Bottom:
  text ".Layer_Name" at 14.656,-21.806 h1.52
M15 Courtyards Top:
  text ".Layer_Name" at 14.656,-21.806 h1.52
M16 Courtyards Bottom:
  text ".Layer_Name" at 14.656,-21.806 h1.52
Drill Drawing:
  circle w0.025: c141.547,78.022 r0.632
  lines w0.025: 140.915,47.048 142.179,47.048 142.179,48.312 140.915,48.312 140.915,47.048 ; 140.915,51.473 141.547,50.841 142.179,51.473 141.547,52.105 140.915,51.473 ; 140.915,54.633 140.915,54.949 141.231,55.265 140.915,55.581 140.915,55.898 141.231,55.898 141.547,55.581 141.863,55.898 142.179,55.898 142.179,55.581 141.863,55.265 142.179,54.949 142.179,54.633 141.863,54.633 141.547,54.949 141.231,54.633 140.915,54.633 ; 140.915,58.742 141.231,58.742 141.231,58.426 141.863,58.426 141.863,58.742 142.179,58.742 142.179,59.374 141.863,59.374 141.863,59.69 141.231,59.69 141.231,59.374 140.915,59.374 140.915,58.742 ; 140.915,62.535 141.231,62.535 141.547,62.219 141.863,62.535 142.179,62.535 141.863,62.851 142.179,63.167 141.863,63.167 141.547,63.483 141.231,63.167 140.915,63.167 141.231,62.851 140.915,62.535 ; 140.915,67.276 142.179,67.276 141.547,66.011 140.915,67.276 ; 140.915,69.804 142.179,69.804 142.179,71.068 140.915,71.068 140.915,69.804 ; 140.915,74.861 142.179,74.861 141.547,73.597 140.915,74.861 ; 140.915,81.182 141.547,81.498 142.179,81.182 141.863,81.814 142.179,82.447 141.547,82.131 140.915,82.447 141.231,81.814 140.915,81.182 ; 141.168,70.057 141.926,70.057 141.926,70.816 141.168,70.816 141.168,70.057 ; 141.168,74.608 141.926,74.608 141.547,73.85 141.168,74.608
  lines w0.305: 139.192,45.91 192.99,45.91 ; 139.192,83.837 192.99,83.837 ; 148.599,42.117 148.599,87.63 ; 157.667,42.117 157.667,87.63 ; 174.471,42.117 174.471,87.63 ; 181.688,42.117 181.688,87.63 ; 139.192,42.117 192.99,42.117 192.99,87.63 139.192,87.63 139.192,42.117
  text "Symbol" at 141.468,84.975 h1.83
  text "Quantity" at 149.737,84.975 h1.83
  text "Finished Hole Size" at 158.805,84.975 h1.83
  text "Plated" at 175.609,84.975 h1.83
  text "Hole Type" at 182.826,84.975 h1.83
  text "2" at 149.737,81.182 h1.52
  text "43.31mil (1.100mm)" at 158.805,81.182 h1.52
  text "NPTH" at 175.609,81.182 h1.52
  text "Round" at 182.826,81.182 h1.52
  text "27" at 149.737,77.39 h1.52
  text "7.87mil (0.200mm)" at 158.805,77.39 h1.52
  text "PTH" at 175.609,77.39 h1.52
  text "Round" at 182.826,77.39 h1.52
  text "96" at 149.737,73.597 h1.52
  text "11.81mil (0.300mm)" at 158.805,73.597 h1.52
  text "PTH" at 175.609,73.597 h1.52
  text "Round" at 182.826,73.597 h1.52
  text "203" at 149.737,69.804 h1.52
  text "12.00mil (0.305mm)" at 158.805,69.804 h1.52
  text "PTH" at 175.609,69.804 h1.52
  text "Round" at 182.826,69.804 h1.52
  text "12" at 149.737,66.011 h1.52
  text "39.37mil (1.000mm)" at 158.805,66.011 h1.52
  text "PTH" at 175.609,66.011 h1.52
  text "Round" at 182.826,66.011 h1.52
  text "21" at 149.737,62.219 h1.52
  text "40.00mil (1.016mm)" at 158.805,62.219 h1.52
  text "PTH" at 175.609,62.219 h1.52
  text "Round" at 182.826,62.219 h1.52
  text "2" at 149.737,58.426 h1.52
  text "43.31mil (1.100mm)" at 158.805,58.426 h1.52
  text "PTH" at 175.609,58.426 h1.52
  text "Round" at 182.826,58.426 h1.52
  text "12" at 149.737,54.633 h1.52
  text "51.18mil (1.300mm)" at 158.805,54.633 h1.52
  text "PTH" at 175.609,54.633 h1.52
  text "Round" at 182.826,54.633 h1.52
  text "2" at 149.737,50.841 h1.52
  text "63.00mil (1.600mm)" at 158.805,50.841 h1.52
  text "PTH" at 175.609,50.841 h1.52
  text "Round" at 182.826,50.841 h1.52
  text "4" at 149.737,47.048 h1.52
  text "125.98mil (3.200mm)" at 158.805,47.048 h1.52
  text "PTH" at 175.609,47.048 h1.52
  text "Round" at 182.826,47.048 h1.52
  text "381 Total" at 149.737,43.255 h1.52
  text ".Layer_Name" at 14.656,-21.806 h1.52

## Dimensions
0,0 to 111.76,0 on M2 Board Dimensions
0,0 to 0,61.722 on M2 Board Dimensions
0,-10.16 to 25.4,-10.16 on M2 Board Dimensions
